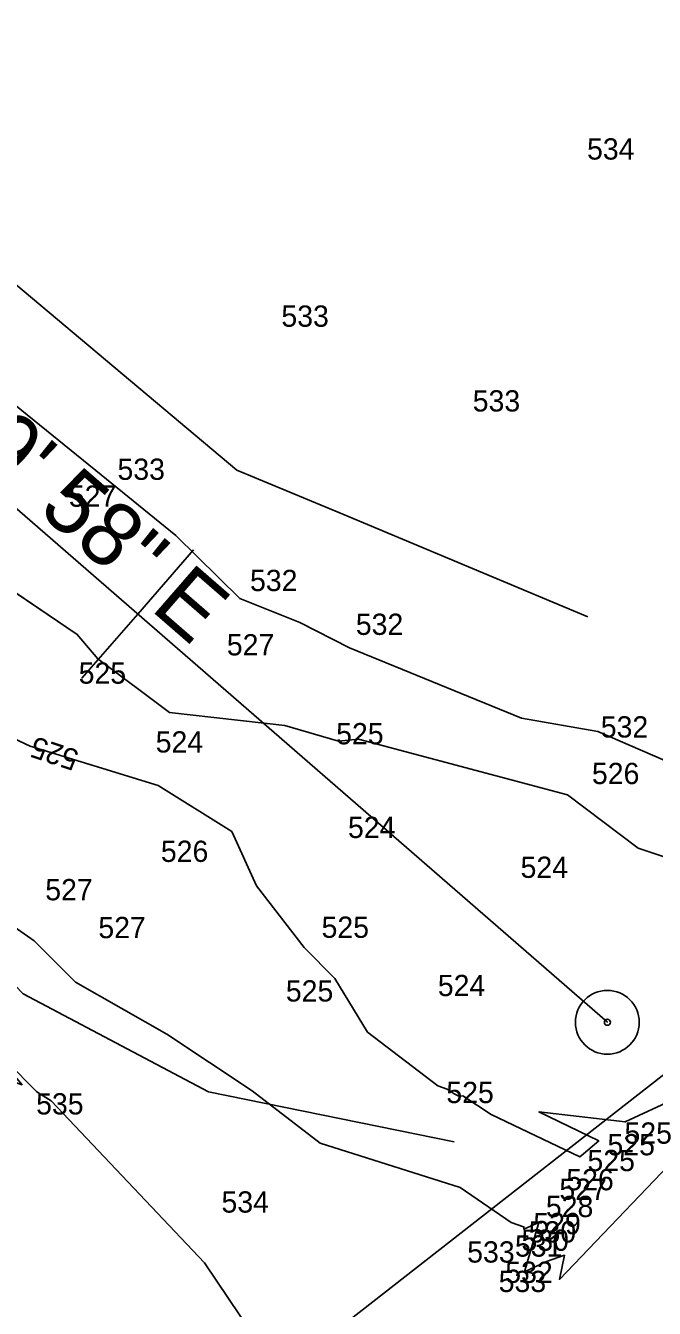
# Model space of a CAD drawing. Extents: x 1787461 to 1970323, y 938412 to 1118748.
# Drawn here: x 1967774.9 to 1967834, y 1117447.9 to 1117568.5 of the extents above; entities that cross this region are included whole.
import ezdxf

# ---------------------------------------------------------------- set-up
doc = ezdxf.new("R2010")
doc.units = 0
for name, color, linetype in [('Default', 7, 'Continuous'), ('HHA ADDITIONAL XSs', 7, 'Continuous'), ('RD_EX_DV_Prop', 7, 'Continuous'), ('RD_EX_H2O', 7, 'Continuous'), ('RD_HC_CL', 7, 'Continuous'), ('RD_HC_Data', 7, 'Continuous'), ('RD_HC_Data_Tic', 7, 'Continuous'), ('RD_SMD_Locator', 7, 'Continuous')]:
    doc.layers.add(name, color=color, linetype=linetype)

msp = doc.modelspace()

# ---------------------------------------------------------------- linework, layer by layer
at = {"layer": 'Default'}
for points in [[(1967864.09, 1117491.4), (1967860.39, 1117488.79), (1967857.14, 1117486.78), (1967853.13, 1117483.68), (1967853.29, 1117484.04), (1967852.82, 1117483.54), (1967852.36, 1117483.18), (1967846.09, 1117488.43), (1967845.27, 1117490.67), (1967846.19, 1117494.55), (1967828.68, 1117502.13), (1967821.49, 1117503.37), (1967805.34, 1117509.98), (1967800.65, 1117512.37), (1967795, 1117514.63), (1967789.01, 1117520.57), (1967781.48, 1117526.67), (1967771.5, 1117534.74), (1967762.73, 1117543.19), (1967757.96, 1117556.81), (1967755.44, 1117564.85), (1967761.67, 1117572.63)], [(1967864.09, 1117491.4), (1967860.39, 1117488.79), (1967857.14, 1117486.78), (1967853.13, 1117483.68), (1967853.29, 1117484.04), (1967852.82, 1117483.54), (1967852.36, 1117483.18), (1967846.09, 1117488.43), (1967845.27, 1117490.67), (1967846.19, 1117494.55), (1967828.68, 1117502.13), (1967821.49, 1117503.37), (1967805.34, 1117509.98), (1967800.65, 1117512.37), (1967795, 1117514.63), (1967789.01, 1117520.57), (1967781.48, 1117526.67), (1967771.5, 1117534.74), (1967762.73, 1117543.19), (1967757.96, 1117556.81), (1967755.44, 1117564.85), (1967761.67, 1117572.63)], [(1967864.09, 1117491.4), (1967860.39, 1117488.79), (1967857.14, 1117486.78), (1967853.13, 1117483.68), (1967853.29, 1117484.04), (1967852.82, 1117483.54), (1967852.36, 1117483.18), (1967846.09, 1117488.43), (1967845.27, 1117490.67), (1967846.19, 1117494.55), (1967828.68, 1117502.13), (1967821.49, 1117503.37), (1967805.34, 1117509.98), (1967800.65, 1117512.37), (1967795, 1117514.63), (1967789.01, 1117520.57), (1967781.48, 1117526.67), (1967771.5, 1117534.74), (1967762.73, 1117543.19), (1967757.96, 1117556.81), (1967755.44, 1117564.85), (1967761.67, 1117572.63)], [(1967864.09, 1117491.4), (1967860.39, 1117488.79), (1967857.14, 1117486.78), (1967853.13, 1117483.68), (1967853.29, 1117484.04), (1967852.82, 1117483.54), (1967852.36, 1117483.18), (1967846.09, 1117488.43), (1967845.27, 1117490.67), (1967846.19, 1117494.55), (1967828.68, 1117502.13), (1967821.49, 1117503.37), (1967805.34, 1117509.98), (1967800.65, 1117512.37), (1967795, 1117514.63), (1967789.01, 1117520.57), (1967781.48, 1117526.67), (1967771.5, 1117534.74), (1967762.73, 1117543.19), (1967757.96, 1117556.81), (1967755.44, 1117564.85), (1967761.67, 1117572.63)], [(1967864.09, 1117491.4), (1967860.39, 1117488.79), (1967857.14, 1117486.78), (1967853.13, 1117483.68), (1967853.29, 1117484.04), (1967852.82, 1117483.54), (1967852.36, 1117483.18), (1967846.09, 1117488.43), (1967845.27, 1117490.67), (1967846.19, 1117494.55), (1967828.68, 1117502.13), (1967821.49, 1117503.37), (1967805.34, 1117509.98), (1967800.65, 1117512.37), (1967795, 1117514.63), (1967789.01, 1117520.57), (1967781.48, 1117526.67), (1967771.5, 1117534.74), (1967762.73, 1117543.19), (1967757.96, 1117556.81), (1967755.44, 1117564.85), (1967761.67, 1117572.63)], [(1967864.09, 1117491.4), (1967860.39, 1117488.79), (1967857.14, 1117486.78), (1967853.13, 1117483.68), (1967853.29, 1117484.04), (1967852.82, 1117483.54), (1967852.36, 1117483.18), (1967846.09, 1117488.43), (1967845.27, 1117490.67), (1967846.19, 1117494.55), (1967828.68, 1117502.13), (1967821.49, 1117503.37), (1967805.34, 1117509.98), (1967800.65, 1117512.37), (1967795, 1117514.63), (1967789.01, 1117520.57), (1967781.48, 1117526.67), (1967771.5, 1117534.74), (1967762.73, 1117543.19), (1967757.96, 1117556.81), (1967755.44, 1117564.85), (1967761.67, 1117572.63)], [(1967864.09, 1117491.4), (1967860.39, 1117488.79), (1967857.14, 1117486.78), (1967853.13, 1117483.68), (1967853.29, 1117484.04), (1967852.82, 1117483.54), (1967852.36, 1117483.18), (1967846.09, 1117488.43), (1967845.27, 1117490.67), (1967846.19, 1117494.55), (1967828.68, 1117502.13), (1967821.49, 1117503.37), (1967805.34, 1117509.98), (1967800.65, 1117512.37), (1967795, 1117514.63), (1967789.01, 1117520.57), (1967781.48, 1117526.67), (1967771.5, 1117534.74), (1967762.73, 1117543.19), (1967757.96, 1117556.81), (1967755.44, 1117564.85), (1967761.67, 1117572.63)], [(1967837.86, 1117489.36), (1967832.47, 1117491.15), (1967825.83, 1117496.16), (1967806.17, 1117501.4), (1967804.28, 1117501.23), (1967799.24, 1117502.7), (1967788.4, 1117503.91), (1967781.65, 1117508.96), (1967779.72, 1117511.26), (1967768.31, 1117518.95), (1967764.64, 1117516.68), (1967759.43, 1117524.47), (1967759.27, 1117525.73), (1967760.24, 1117527.88), (1967757.73, 1117542.36), (1967754.45, 1117550.79), (1967750.76, 1117565.39)], [(1967703.15, 1117559.88), (1967721.29, 1117507.74), (1967726.43, 1117513.31), (1967726.84, 1117512.62), (1967730.47, 1117509.37), (1967733.85, 1117499.01), (1967748.51, 1117494.25), (1967757.67, 1117474.76), (1967774.54, 1117468.91), (1967770.4, 1117473.79), (1967775.91, 1117468.26), (1967776.03, 1117468.19), (1967777.26, 1117467.38), (1967791.69, 1117452.17), (1967799.51, 1117440.56), (1967803.01, 1117436.4), (1967803.55, 1117436.04), (1967803.99, 1117435.25), (1967807.61, 1117433.26)], [(1967707.45, 1117547.54), (1967721.29, 1117507.74), (1967726.43, 1117513.31), (1967726.84, 1117512.62), (1967730.47, 1117509.37), (1967733.85, 1117499.01), (1967748.51, 1117494.25), (1967757.67, 1117474.76), (1967774.54, 1117468.91), (1967770.4, 1117473.79), (1967775.91, 1117468.26), (1967776.03, 1117468.19), (1967777.26, 1117467.38), (1967791.69, 1117452.17), (1967799.51, 1117440.56), (1967803.01, 1117436.4), (1967803.55, 1117436.04), (1967803.99, 1117435.25), (1967807.61, 1117433.26)], [(1967707.45, 1117547.54), (1967721.29, 1117507.74), (1967726.43, 1117513.31), (1967726.84, 1117512.62), (1967730.47, 1117509.37), (1967733.85, 1117499.01), (1967748.51, 1117494.25), (1967757.67, 1117474.76), (1967774.54, 1117468.91), (1967770.4, 1117473.79), (1967775.91, 1117468.26), (1967776.03, 1117468.19), (1967777.26, 1117467.38), (1967791.69, 1117452.17), (1967799.51, 1117440.56), (1967803.01, 1117436.4), (1967803.55, 1117436.04), (1967803.99, 1117435.25), (1967807.61, 1117433.26)], [(1967707.45, 1117547.54), (1967721.29, 1117507.74), (1967726.43, 1117513.31), (1967726.84, 1117512.62), (1967730.47, 1117509.37), (1967733.85, 1117499.01), (1967748.51, 1117494.25), (1967757.67, 1117474.76), (1967774.54, 1117468.91), (1967770.4, 1117473.79), (1967775.91, 1117468.26), (1967776.03, 1117468.19), (1967777.26, 1117467.38), (1967791.69, 1117452.17), (1967799.51, 1117440.56), (1967803.01, 1117436.4), (1967803.55, 1117436.04), (1967803.99, 1117435.25), (1967807.61, 1117433.26)], [(1967707.45, 1117547.54), (1967721.29, 1117507.74), (1967726.43, 1117513.31), (1967726.84, 1117512.62), (1967730.47, 1117509.37), (1967733.85, 1117499.01), (1967748.51, 1117494.25), (1967757.67, 1117474.76), (1967774.54, 1117468.91), (1967770.4, 1117473.79), (1967775.91, 1117468.26), (1967776.03, 1117468.19), (1967777.26, 1117467.38), (1967791.69, 1117452.17), (1967799.51, 1117440.56), (1967803.01, 1117436.4), (1967803.55, 1117436.04), (1967803.99, 1117435.25), (1967807.61, 1117433.26)], [(1967707.45, 1117547.54), (1967721.29, 1117507.74), (1967726.43, 1117513.31), (1967726.84, 1117512.62), (1967730.47, 1117509.37), (1967733.85, 1117499.01), (1967748.51, 1117494.25), (1967757.67, 1117474.76), (1967774.54, 1117468.91), (1967770.4, 1117473.79), (1967775.91, 1117468.26), (1967776.03, 1117468.19), (1967777.26, 1117467.38), (1967791.69, 1117452.17), (1967799.51, 1117440.56), (1967803.01, 1117436.4), (1967803.55, 1117436.04), (1967803.99, 1117435.25), (1967807.61, 1117433.26)], [(1967707.45, 1117547.54), (1967721.29, 1117507.74), (1967726.43, 1117513.31), (1967726.84, 1117512.62), (1967730.47, 1117509.37), (1967733.85, 1117499.01), (1967748.51, 1117494.25), (1967757.67, 1117474.76), (1967774.54, 1117468.91), (1967770.4, 1117473.79), (1967775.91, 1117468.26), (1967776.03, 1117468.19), (1967777.26, 1117467.38), (1967791.69, 1117452.17), (1967799.51, 1117440.56), (1967803.01, 1117436.4), (1967803.55, 1117436.04), (1967803.99, 1117435.25), (1967807.61, 1117433.26)], [(1967837.86, 1117489.36), (1967832.47, 1117491.15), (1967825.83, 1117496.16), (1967806.17, 1117501.4), (1967804.28, 1117501.23), (1967799.24, 1117502.7), (1967788.4, 1117503.91), (1967781.65, 1117508.96), (1967779.72, 1117511.26), (1967771.37, 1117516.88)], [(1967837.86, 1117489.36), (1967832.47, 1117491.15), (1967825.83, 1117496.16), (1967806.17, 1117501.4), (1967804.28, 1117501.23), (1967799.24, 1117502.7), (1967788.4, 1117503.91), (1967781.65, 1117508.96), (1967779.72, 1117511.26), (1967771.37, 1117516.88)], [(1967837.86, 1117489.36), (1967832.47, 1117491.15), (1967825.83, 1117496.16), (1967806.17, 1117501.4), (1967804.28, 1117501.23), (1967799.24, 1117502.7), (1967788.4, 1117503.91), (1967781.65, 1117508.96), (1967779.72, 1117511.26), (1967771.37, 1117516.88)], [(1967837.86, 1117489.36), (1967832.47, 1117491.15), (1967825.83, 1117496.16), (1967806.17, 1117501.4), (1967804.28, 1117501.23), (1967799.24, 1117502.7), (1967788.4, 1117503.91), (1967781.65, 1117508.96), (1967779.72, 1117511.26), (1967771.37, 1117516.88)], [(1967837.86, 1117489.36), (1967832.47, 1117491.15), (1967825.83, 1117496.16), (1967806.17, 1117501.4), (1967804.28, 1117501.23), (1967799.24, 1117502.7), (1967788.4, 1117503.91), (1967781.65, 1117508.96), (1967779.72, 1117511.26), (1967771.37, 1117516.88)], [(1967837.86, 1117489.36), (1967832.47, 1117491.15), (1967825.83, 1117496.16), (1967806.17, 1117501.4), (1967804.28, 1117501.23), (1967799.24, 1117502.7), (1967788.4, 1117503.91), (1967781.65, 1117508.96), (1967779.72, 1117511.26), (1967771.37, 1117516.88)], [(1967770.08, 1117503.2), (1967775.29, 1117500.76), (1967787.34, 1117497.06), (1967794.26, 1117492.71), (1967796.58, 1117487.61), (1967801.07, 1117481.81), (1967803.95, 1117478.89), (1967807.03, 1117473.86), (1967813.63, 1117468.79), (1967814.52, 1117468.5), (1967815.18, 1117468.05), (1967815.6, 1117467.84), (1967815.98, 1117467.86), (1967818.66, 1117466.1), (1967826.98, 1117462.12), (1967827.34, 1117462.4), (1967828.76, 1117463.62), (1967823.14, 1117466.35), (1967830.72, 1117465.47), (1967831.24, 1117465.43), (1967831.33, 1117465.51), (1967831.24, 1117465.41), (1967835.98, 1117467.62)], [(1967780.09, 1117499.28), (1967787.34, 1117497.06), (1967794.26, 1117492.71), (1967796.58, 1117487.61), (1967801.07, 1117481.81), (1967803.95, 1117478.89), (1967807.03, 1117473.86), (1967813.63, 1117468.79), (1967814.52, 1117468.5), (1967815.18, 1117468.05), (1967815.6, 1117467.84), (1967815.98, 1117467.86), (1967818.66, 1117466.1), (1967826.98, 1117462.12), (1967827.34, 1117462.4), (1967828.76, 1117463.62), (1967823.14, 1117466.35), (1967830.72, 1117465.47), (1967831.24, 1117465.43), (1967831.33, 1117465.51), (1967831.24, 1117465.41), (1967835.98, 1117467.62)], [(1967780.09, 1117499.28), (1967787.34, 1117497.06), (1967794.26, 1117492.71), (1967796.58, 1117487.61), (1967801.07, 1117481.81), (1967803.95, 1117478.89), (1967807.03, 1117473.86), (1967813.63, 1117468.79), (1967814.52, 1117468.5), (1967815.18, 1117468.05), (1967815.6, 1117467.84), (1967815.98, 1117467.86), (1967818.66, 1117466.1), (1967826.98, 1117462.12), (1967827.34, 1117462.4), (1967828.76, 1117463.62), (1967823.14, 1117466.35), (1967830.72, 1117465.47), (1967831.24, 1117465.43), (1967831.33, 1117465.51), (1967831.24, 1117465.41), (1967835.98, 1117467.62)], [(1967780.09, 1117499.28), (1967787.34, 1117497.06), (1967794.26, 1117492.71), (1967796.58, 1117487.61), (1967801.07, 1117481.81), (1967803.95, 1117478.89), (1967807.03, 1117473.86), (1967813.63, 1117468.79), (1967814.52, 1117468.5), (1967815.18, 1117468.05), (1967815.6, 1117467.84), (1967815.98, 1117467.86), (1967818.66, 1117466.1), (1967826.98, 1117462.12), (1967827.34, 1117462.4), (1967828.76, 1117463.62), (1967823.14, 1117466.35), (1967830.72, 1117465.47), (1967831.24, 1117465.43), (1967831.33, 1117465.51), (1967831.24, 1117465.41), (1967835.98, 1117467.62)], [(1967780.09, 1117499.28), (1967787.34, 1117497.06), (1967794.26, 1117492.71), (1967796.58, 1117487.61), (1967801.07, 1117481.81), (1967803.95, 1117478.89), (1967807.03, 1117473.86), (1967813.63, 1117468.79), (1967814.52, 1117468.5), (1967815.18, 1117468.05), (1967815.6, 1117467.84), (1967815.98, 1117467.86), (1967818.66, 1117466.1), (1967826.98, 1117462.12), (1967827.34, 1117462.4), (1967828.76, 1117463.62), (1967823.14, 1117466.35), (1967830.72, 1117465.47), (1967831.24, 1117465.43), (1967831.33, 1117465.51), (1967831.24, 1117465.41), (1967835.98, 1117467.62)], [(1967780.09, 1117499.28), (1967787.34, 1117497.06), (1967794.26, 1117492.71), (1967796.58, 1117487.61), (1967801.07, 1117481.81), (1967803.95, 1117478.89), (1967807.03, 1117473.86), (1967813.63, 1117468.79), (1967814.52, 1117468.5), (1967815.18, 1117468.05), (1967815.6, 1117467.84), (1967815.98, 1117467.86), (1967818.66, 1117466.1), (1967826.98, 1117462.12), (1967827.34, 1117462.4), (1967828.76, 1117463.62), (1967823.14, 1117466.35), (1967830.72, 1117465.47), (1967831.24, 1117465.43), (1967831.33, 1117465.51), (1967831.24, 1117465.41), (1967835.98, 1117467.62)], [(1967780.09, 1117499.28), (1967787.34, 1117497.06), (1967794.26, 1117492.71), (1967796.58, 1117487.61), (1967801.07, 1117481.81), (1967803.95, 1117478.89), (1967807.03, 1117473.86), (1967813.63, 1117468.79), (1967814.52, 1117468.5), (1967815.18, 1117468.05), (1967815.6, 1117467.84), (1967815.98, 1117467.86), (1967818.66, 1117466.1), (1967826.98, 1117462.12), (1967827.34, 1117462.4), (1967828.76, 1117463.62), (1967823.14, 1117466.35), (1967830.72, 1117465.47), (1967831.24, 1117465.43), (1967831.33, 1117465.51), (1967831.24, 1117465.41), (1967835.98, 1117467.62)], [(1967760.21, 1117493.2), (1967772.53, 1117484.63), (1967775.68, 1117482.44), (1967779.55, 1117478.56), (1967788.15, 1117473.67), (1967796.17, 1117468.34), (1967802.58, 1117463.41), (1967815.73, 1117459.23), (1967820.53, 1117455.96), (1967821.67, 1117455.55), (1967821.73, 1117455.57), (1967821.73, 1117455.32), (1967823.12, 1117455.95), (1967821.79, 1117451.31), (1967823.86, 1117452.27), (1967825.53, 1117452.87), (1967825.06, 1117450.6), (1967864.09, 1117491.4)], [(1967760.21, 1117493.2), (1967772.53, 1117484.63), (1967775.68, 1117482.44), (1967779.55, 1117478.56), (1967788.15, 1117473.67), (1967796.17, 1117468.34), (1967802.58, 1117463.41), (1967815.73, 1117459.23), (1967820.53, 1117455.96), (1967821.67, 1117455.55), (1967821.73, 1117455.57), (1967821.73, 1117455.32), (1967823.12, 1117455.95), (1967821.79, 1117451.31), (1967823.86, 1117452.27), (1967825.53, 1117452.87), (1967825.06, 1117450.6), (1967864.09, 1117491.4)], [(1967760.21, 1117493.2), (1967772.53, 1117484.63), (1967775.68, 1117482.44), (1967779.55, 1117478.56), (1967788.15, 1117473.67), (1967796.17, 1117468.34), (1967802.58, 1117463.41), (1967815.73, 1117459.23), (1967820.53, 1117455.96), (1967821.67, 1117455.55), (1967821.73, 1117455.57), (1967821.73, 1117455.32), (1967823.12, 1117455.95), (1967821.79, 1117451.31), (1967823.86, 1117452.27), (1967825.53, 1117452.87), (1967825.06, 1117450.6), (1967864.09, 1117491.4)], [(1967760.21, 1117493.2), (1967772.53, 1117484.63), (1967775.68, 1117482.44), (1967779.55, 1117478.56), (1967788.15, 1117473.67), (1967796.17, 1117468.34), (1967802.58, 1117463.41), (1967815.73, 1117459.23), (1967820.53, 1117455.96), (1967821.67, 1117455.55), (1967821.73, 1117455.57), (1967821.73, 1117455.32), (1967823.12, 1117455.95), (1967821.79, 1117451.31), (1967823.86, 1117452.27), (1967825.53, 1117452.87), (1967825.06, 1117450.6), (1967864.09, 1117491.4)], [(1967760.21, 1117493.2), (1967772.53, 1117484.63), (1967775.68, 1117482.44), (1967779.55, 1117478.56), (1967788.15, 1117473.67), (1967796.17, 1117468.34), (1967802.58, 1117463.41), (1967815.73, 1117459.23), (1967820.53, 1117455.96), (1967821.67, 1117455.55), (1967821.73, 1117455.57), (1967821.73, 1117455.32), (1967823.12, 1117455.95), (1967821.79, 1117451.31), (1967823.86, 1117452.27), (1967825.53, 1117452.87), (1967825.06, 1117450.6), (1967864.09, 1117491.4)], [(1967760.21, 1117493.2), (1967772.53, 1117484.63), (1967775.68, 1117482.44), (1967779.55, 1117478.56), (1967788.15, 1117473.67), (1967796.17, 1117468.34), (1967802.58, 1117463.41), (1967815.73, 1117459.23), (1967820.53, 1117455.96), (1967821.67, 1117455.55), (1967821.73, 1117455.57), (1967821.73, 1117455.32), (1967823.12, 1117455.95), (1967821.79, 1117451.31), (1967823.86, 1117452.27), (1967825.53, 1117452.87), (1967825.06, 1117450.6), (1967864.09, 1117491.4)], [(1967772.53, 1117484.63), (1967775.68, 1117482.44), (1967779.55, 1117478.56), (1967788.15, 1117473.67), (1967796.17, 1117468.34), (1967802.58, 1117463.41), (1967815.73, 1117459.23), (1967820.53, 1117455.96), (1967821.67, 1117455.55), (1967821.73, 1117455.57), (1967821.73, 1117455.32), (1967823.12, 1117455.95), (1967821.79, 1117451.31), (1967823.86, 1117452.27), (1967825.53, 1117452.87), (1967825.06, 1117450.6), (1967864.09, 1117491.4)]]:
    msp.add_lwpolyline(points, dxfattribs=at)
at = {"layer": 'HHA ADDITIONAL XSs'}
msp.add_lwpolyline([(1969426.56, 1117649.38), (1968158.01, 1117641.45), (1967943.24, 1117548.13), (1967889.71, 1117512.72), (1967718.24, 1117378.75)], dxfattribs=at)
at = {"layer": 'RD_EX_DV_Prop'}
msp.add_line((1967728.08, 1117563.01), (1967829.57, 1117474.78), dxfattribs=at)
at = {"layer": 'RD_EX_H2O'}
for points in [[(1967793.07, 1117884.81), (1967795.4, 1117862.79), (1967808.44, 1117844.76), (1967827.6, 1117817.64), (1967803.85, 1117763.92), (1967785.1, 1117717.4), (1967778.96, 1117698.7), (1967761.45, 1117660.55), (1967735.16, 1117625.66), (1967726.1, 1117620.57), (1967713.81, 1117582.71), (1967729.78, 1117524.09), (1967774.63, 1117477.47), (1967792.06, 1117468.24), (1967815.16, 1117463.54)], [(1967872.32, 1117822.66), (1967872.31, 1117820.09), (1967867.75, 1117800.84), (1967855.06, 1117765.41), (1967833.55, 1117731.08), (1967814.13, 1117687.88), (1967798.73, 1117637.75), (1967777.02, 1117596.99), (1967770.1, 1117591.47), (1967755.23, 1117573.96), (1967763.13, 1117553.21), (1967794.74, 1117526.69), (1967804.69, 1117522.56), (1967827.72, 1117512.92)]]:
    msp.add_lwpolyline(points, dxfattribs=at)
at = {"layer": 'RD_HC_CL'}
msp.add_line((1967728.08, 1117563.01), (1967829.57, 1117474.78), dxfattribs=at)
at = {"layer": 'RD_HC_Data'}
for radius in [3, 0.282]:
    msp.add_circle((1967829.57, 1117474.78), radius, dxfattribs=at)
at = {"layer": 'RD_HC_Data_Tic'}
for q in [(1967790.66, 1117519.21), (1967780.17, 1117507.13)]:
    msp.add_line((1967785.42, 1117513.17), q, dxfattribs=at)
at = {"layer": 'RD_SMD_Locator'}
msp.add_circle((1967829.57, 1117474.78), 0.001, dxfattribs=at)

# ---------------------------------------------------------------- texts
at = {"layer": 'Default'}
for s, p in [('534', (1967827.66, 1117555.91)), ('533', (1967798.92, 1117540.19)), ('533', (1967816.91, 1117532.22)), ('533', (1967783.51, 1117525.79)), ('527', (1967778.94, 1117523.26)), ('532', (1967795.97, 1117515.33)), ('532', (1967805.92, 1117511.21)), ('527', (1967793.79, 1117509.28)), ('525', (1967779.86, 1117506.62)), ('532', (1967828.95, 1117501.56)), ('524', (1967787.1, 1117500.15)), ('525', (1967804.07, 1117500.92)), ('526', (1967828.12, 1117497.18)), ('524', (1967805.18, 1117492.11)), ('526', (1967787.59, 1117489.86)), ('524', (1967821.41, 1117488.36)), ('527', (1967776.72, 1117486.25)), ('527', (1967781.71, 1117482.69)), ('525', (1967802.7, 1117482.72)), ('524', (1967813.63, 1117477.24)), ('525', (1967799.34, 1117476.73)), ('525', (1967814.43, 1117467.18)), ('535', (1967775.86, 1117466.11)), ('525', (1967831.18, 1117463.36)), ('525', (1967829.58, 1117462.27)), ('525', (1967827.7, 1117460.78)), ('527', (1967825.06, 1117458.08)), ('526', (1967825.71, 1117458.98)), ('534', (1967793.29, 1117456.88)), ('528', (1967823.79, 1117456.46)), ('529', (1967822.61, 1117454.85)), ('530', (1967821.49, 1117453.29)), ('530', (1967822.17, 1117454.07)), ('533', (1967816.39, 1117452.18)), ('531', (1967820.88, 1117452.74)), ('533', (1967819.35, 1117449.41)), ('532', (1967819.97, 1117450.27))]:
    msp.add_text(s, height=2, dxfattribs=at).set_placement(p)
msp.add_text('525', height=2, rotation=161.6503, dxfattribs=at).set_placement((1967780.01, 1117500.29))
msp.add_text('525', height=2, rotation=161.6503, dxfattribs=at).set_placement((1967780.01, 1117500.29))
msp.add_text('525', height=2, rotation=161.6503, dxfattribs=at).set_placement((1967780.01, 1117500.29))
msp.add_text('525', height=2, rotation=161.6503, dxfattribs=at).set_placement((1967780.01, 1117500.29))
msp.add_text('525', height=2, rotation=161.6503, dxfattribs=at).set_placement((1967780.01, 1117500.29))
msp.add_text('525', height=2, rotation=161.6503, dxfattribs=at).set_placement((1967780.01, 1117500.29))
at = {"layer": 'RD_HC_Data'}
msp.add_text('S 48%%d 59\' 58" E', height=6, rotation=318.9993, dxfattribs=at).set_placement((1967749.8, 1117545.54))

doc.saveas('drawing.dxf')
